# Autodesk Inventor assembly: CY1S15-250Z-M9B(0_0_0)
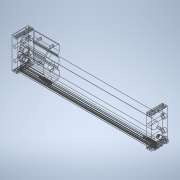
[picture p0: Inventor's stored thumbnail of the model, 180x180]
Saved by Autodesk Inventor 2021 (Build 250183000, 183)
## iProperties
Part Number: CY1S15-250Z-M9B(0_0_0)
Catalog Web Link: www.cadenas.de
Description: CY1S-Z-Magnetically Coupled Rodless Cylinder Slider Type/Slide Bearing
Vendor: SMC
Document SubType Name: Assembly
Designer: partserver
Manufacturer: SMC
Mass: 343.697 g
Surface Area: 1140.92 cm^2
Volume: 343.697 cm^3
Density: 1 g/cm^3
Category: PARTsolutions
Company: SMC
PSOL_IDENT_0: {$CADENAS_DATA\23d-libs\smc_jp\actuator\rodless_cylinders\cy1\cy1s_z_asmtab.prj},275 {VTYP=3D},{STYP=
PSOL_IDENT_1: ASSTAB},{NB=CY1S15-250Z-M9B(0_0_0)},{LINA=CY1S15-250Z-M9B},{NN=CY1S-Z},{DATE=12.02.2021 08:48:21},{G
PSOL_IDENT_2: EOMDATE=09.03.2020 08:58:35},{VERSION=},{LINEID=30},{WBVAR=PIPING,THREAD1,AUTOSWITCH,LEAD,NUMBER,STR
PSOL_IDENT_3: OKE,POS,STOPPER,STOP,OMSC,THREAD2},{WBNUMERIC=STROKE,POS}  {NB=CY1S15-250Z-M9B(0_0_0)},{LINA=CY1S15-
PSOL_IDENT_4: 250Z-M9B},{KT=DUMMY},{BORE=15},{PIPING=},{THREAD1=},{THREAD1X='','(-) M thread'},{AUTOSWITCH=-M9B},{
PSOL_IDENT_5: LEAD=},{LEADX='','(-) 0.5 m','M','(M) 1 m','L','(L) 3 m','Z','(Z) 5 m'},{NUMBER=},{STROKE=250},{STRO
PSOL_IDENT_6: KEX=50,100,150,200,250,300,350,400,450,500},{POS=0},{STOPPER=},{NUMBERX='', '(-) 2 pcs','S', '(S) 1
PSOL_IDENT_7: pc'},{STOP=0},{COM=-},{OMSC=},{THREAD2=0},{STDSTROKE=50,100,150,200,250,300,350,400,450,500},{SMIN=5
PSOL_IDENT_8: 0},{SMAX=750},{ORDER=CY1S15-250Z-M9B},{A=7.5},{B=9.5},{C=5.4},{D=16.6},{D1=12},{E=2},{F=38},{G=6.5},
PSOL_IDENT_9: {GA=5.000},{GB=6},{GP=52},{H=40},{HA=28.0},{HB=29.5},{HC=20.500},{HG=15.000},{HP=39},{HT=20.500},{JJ=
PSOL_IDENT_10: M4x0.7},{K=11.0},{L=60},{LD=5.8},{M=8},{MM=M5x0.8},{NA=10.5},{NB1=16.5},{NC=28.0},{NN=M4x0.7},{P=M5x
PSOL_IDENT_11: 0.8},{PA=30},{PB=50},{PW=75},{Q=75},{QW=30},{R=1.000},{R1=5.500},{S=62},{T=12.5},{UU=M8x1},{W=72},{Y
PSOL_IDENT_12: 1=14.0},{Z=87},{AA=5.5},{AA1=5.500},{AA2=1.500},{BB=56.5},{BB1=56.500},{BB2=60.500},{PPATH=cy1s_z/as
PSOL_IDENT_13: sembly/cy1s_z_asmsbl.prj},{MODEL=CY1S15-250Z-M9B},{NENN=CY1S15-250Z}
NB: CY1S15-250Z-M9B(0_0_0)
NN: CY1S-Z
NT: Magnetically Coupled Rodless Cylinder Slider Type/Slide Bearing
NBSYN: $ORDER.($POS._$STOP._$THREAD2.)
LINA: CY1S15-250Z-M9B
CATALOG: SMC (JP
ROWDESC: CY1S15-250Z
BORE: 15
PIPING: (-) Bilateral piping type
THREAD1: (-) M thread
AUTOSWITCH: M9B Solid state-General-Grommet-Indicator light:Yes-2 wire-In line
LEAD: (-) 0.5 m
NUMBER: (-) 2 pcs
STROKE: 250
POS: 0
STOPPER: (-) Bumper bolt (resin tipped):Mounted on both sides
STOP: Standard stroke
COM: -
OMSC: (-) None
THREAD2: on
SUPPLIER: SMC
ARTICLENO: CY1S15-250Z-M9B(0_0_0)
BOMINFO: CY1S15-250Z-M9B
CREATOR: CADENAS GmbH
Title: CY1S15-250Z-M9B
Author: Cadenas PARTsolutions
Comments: Magnetically Coupled Rodless Cylinder Slider Type/Slide Bearing
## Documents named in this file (6)
- D:\01 Paralaia\Grupos de Traballo\GT Maquetas\CAD 3D\E_Medida\CY1S15-250\CY1S15-250Z-M9B(0_0_0).iam
- D:\01 Paralaia\Grupos de Traballo\GT Maquetas\CAD 3D\E_Medida\CY1S15-250\CY1S15-250Z-M9B(0)_CT.ipt
- D:\01 Paralaia\Grupos de Traballo\GT Maquetas\CAD 3D\E_Medida\CY1S15-250\CY1S15-250Z(0)_BODY.ipt
- D:\01 Paralaia\Grupos de Traballo\GT Maquetas\CAD 3D\E_Medida\CY1S15-250\CY1S15-Z_STOPPER.ipt
- D:\01 Paralaia\Grupos de Traballo\GT Maquetas\CAD 3D\E_Medida\CY1S15-250\BMY3-016_CY1S_Z.ipt
- D:\01 Paralaia\Grupos de Traballo\GT Maquetas\CAD 3D\E_Medida\CY1S15-250\CY1S_Z_D-M9B_SW.ipt
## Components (8 placed, 5 different names)
1. CY1S15-250Z-M9B(0)_CT:1 — Insertar:1, Insertar:2
2. CY1S15-250Z(0)_BODY:1 — Insertar:1, Insertar:2
3. CY1S15-Z_STOPPER:1
4. CY1S15-Z_STOPPER:2
5. BMY3-016_CY1S_Z:1
6. CY1S_Z_D-M9B_SW:1
7. BMY3-016_CY1S_Z:2
8. CY1S_Z_D-M9B_SW:2
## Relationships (2: Insert 2)
- Insertar:1: CY1S15-250Z-M9B(0)_CT:1 ↔ CY1S15-250Z(0)_BODY:1
- Insertar:2: CY1S15-250Z-M9B(0)_CT:1 ↔ CY1S15-250Z(0)_BODY:1
